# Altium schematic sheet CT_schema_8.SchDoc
size 274 x 160 mm
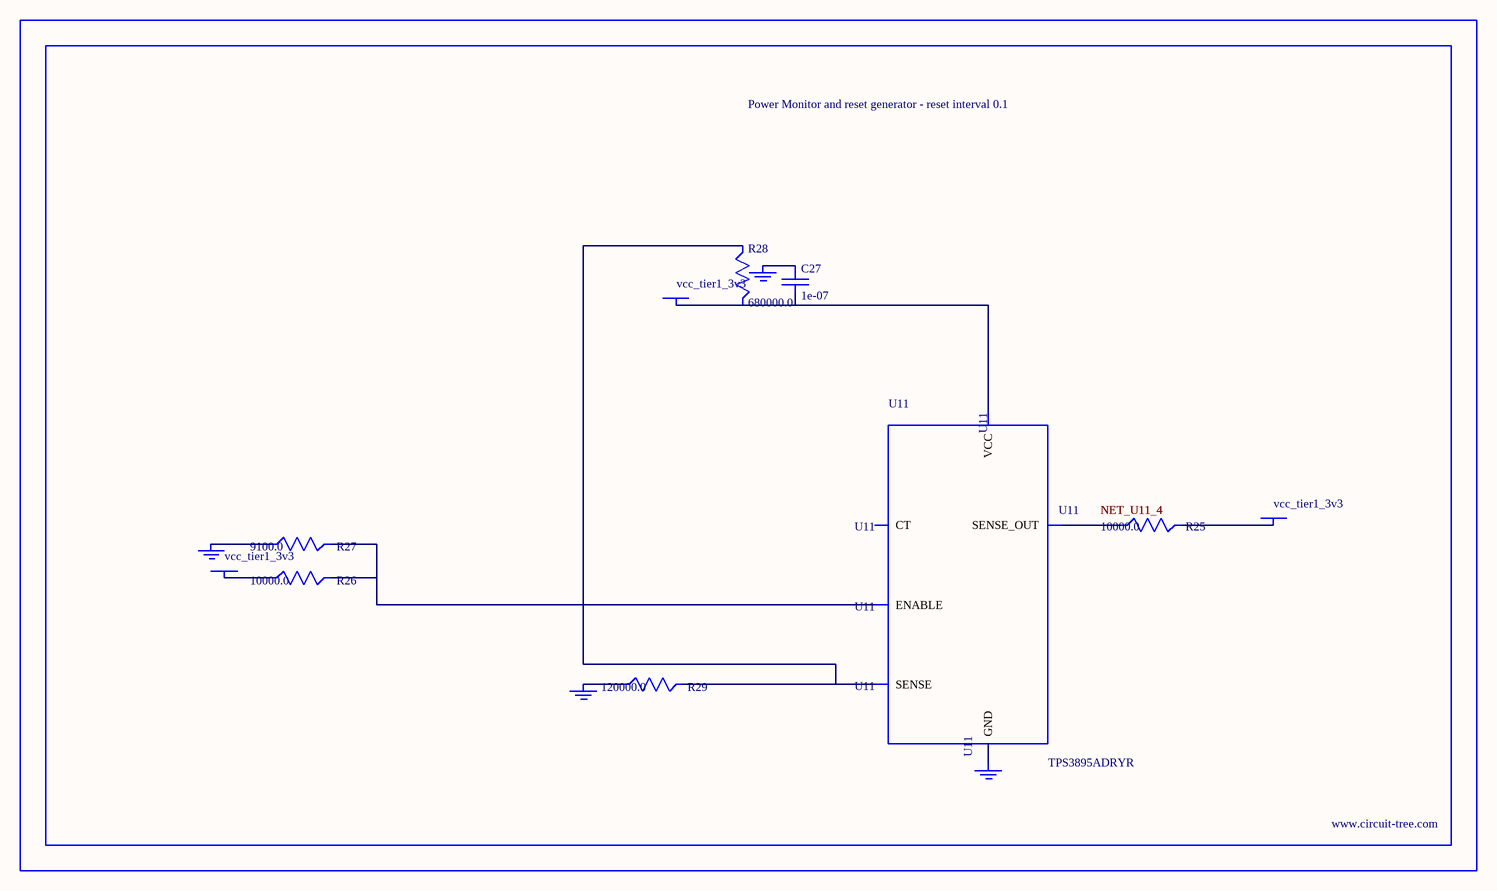
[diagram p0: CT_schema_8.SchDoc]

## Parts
BORDER7  (no value)
C27  1e-07  [C0402]
GND_INSTANCE_7_0  (no value)
GND_INSTANCE_7_1  (no value)
GND_INSTANCE_7_2  (no value)
GND_INSTANCE_7_3  (no value)
POWER_INSTANCE_7_0  vcc_tier1_3v3
POWER_INSTANCE_7_1  vcc_tier1_3v3
POWER_INSTANCE_7_2  vcc_tier1_3v3
R25  10000.0  [R0603]
R26  10000.0  [R0603]
R27  9100.0  [R0603]
R28  680000.0  [R0603]
R29  120000.0  [R0603]
U11  TPS3895ADRYR  [SON-6]

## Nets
NetC27_1: C27.1 GND_INSTANCE_7_2.0(GND)
NetC27_2: C27.2 POWER_INSTANCE_7_2.0(PWR) R28.2 U11.6(VCC)
NetGND_INSTANCE_7_0_0: GND_INSTANCE_7_0.0(GND) R27.1
NetGND_INSTANCE_7_1_0: GND_INSTANCE_7_1.0(GND) R29.1
NetGND_INSTANCE_7_3_0: GND_INSTANCE_7_3.0(GND) U11.2(GND)
NetPOWER_INSTANCE_7_0_0: POWER_INSTANCE_7_0.0(PWR) R26.1
NetPOWER_INSTANCE_7_1_0: POWER_INSTANCE_7_1.0(PWR) R25.2
NetR25_1: R25.1 U11.4(SENSE_OUT)
NetR26_2: R26.2 R27.2 U11.1(ENABLE)
NetR28_1: R28.1 R29.2 U11.3(SENSE)

Not connected (* = marked no-connect by the designer): U11 5(CT)

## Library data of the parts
BORDER7 = BORDER_PAGE7
C27 = C0402C104K3RACTU
GND_INSTANCE_7_0-GND_INSTANCE_7_3 = GND
POWER_INSTANCE_7_0-POWER_INSTANCE_7_2 = PWR
R25 R26 = RC0603JR-0710KL
R27 = RC0603JR-079K1L
R28 = RC0603JR-07680KL
R29 = RC0603JR-07120KL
